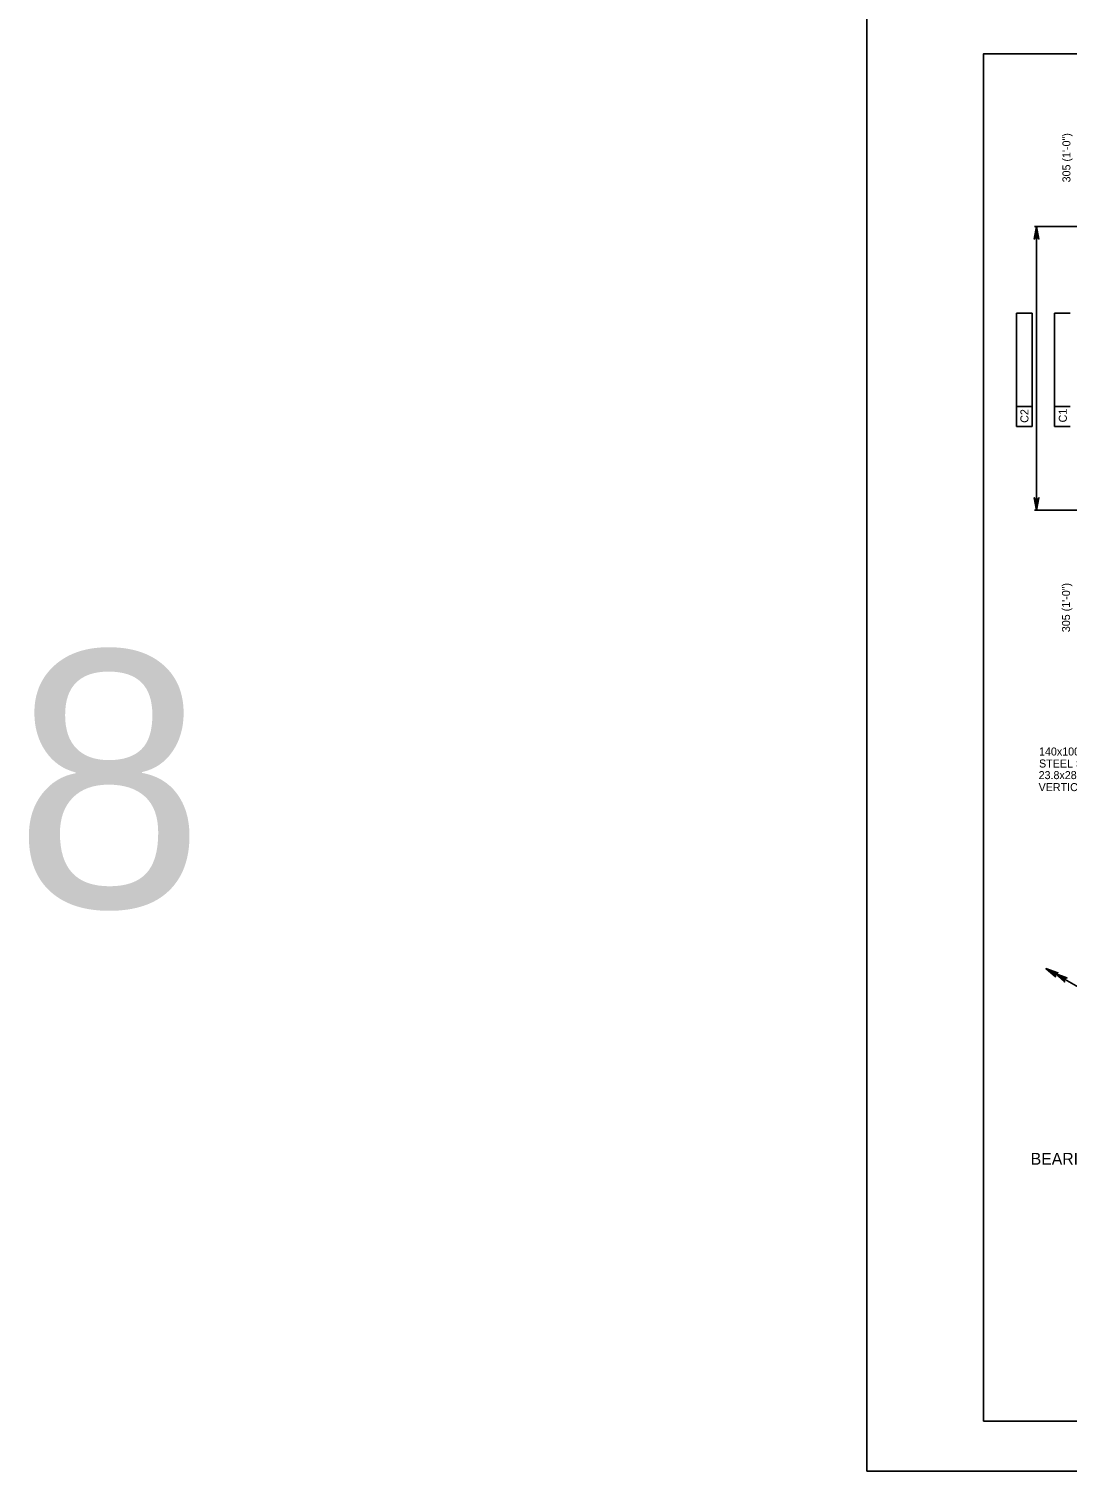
# Model space of a CAD drawing. Extents: x -13 to 81, y -176 to 0.
# Drawn here: x -12.57 to 3.01, y -176 to -154.38 of the extents above; entities that cross this region are included whole.
import ezdxf

# ---------------------------------------------------------------- set-up
doc = ezdxf.new("R2010")
doc.units = 0
for name, color, linetype in [('Level 1', 7, 'Continuous'), ('Level 4', 7, 'Continuous'), ('Level 62', 7, 'Continuous'), ('Level 63', 7, 'Continuous')]:
    doc.layers.add(name, color=color, linetype=linetype)

msp = doc.modelspace()

# ---------------------------------------------------------------- linework, layer by layer
at = {"layer": 'Level 1'}
msp.add_lwpolyline([(1.75, -175.25), (33.25, -175.25), (33.25, -154.75), (1.75, -154.75)], close=True, dxfattribs=at)
at = {"layer": 'Level 4'}
for p, q in [((7.263, -157.34), (2.518, -157.34)), ((2.547, -157.34), (2.547, -161.592)), ((2.483, -158.637), (2.247, -158.637)), ((2.247, -160.035), (2.247, -158.637)), ((2.483, -160.338), (2.483, -158.637)), ((3.05, -158.637), (2.814, -158.637)), ((2.814, -160.035), (2.814, -158.637)), ((2.247, -160.338), (2.247, -160.035)), ((2.483, -160.035), (2.247, -160.035)), ((2.814, -160.338), (2.814, -160.035)), ((3.05, -160.035), (2.814, -160.035)), ((2.247, -160.338), (2.483, -160.338)), ((2.814, -160.338), (3.05, -160.338)), ((9.603, -161.592), (2.518, -161.592)), ((2.688, -168.464), (5.312, -169.971))]:
    msp.add_line(p, q, dxfattribs=at)
for points in [[(2.547, -157.34), (2.582, -157.527), (2.572, -157.513), (2.56, -157.505), (2.547, -157.503), (2.535, -157.505), (2.522, -157.513), (2.512, -157.527), (2.547, -157.34), (2.522, -157.513), (2.535, -157.505), (2.547, -157.34), (2.547, -157.503), (2.56, -157.505), (2.547, -157.34), (2.572, -157.513)], [(2.547, -161.592), (2.512, -161.406), (2.522, -161.42), (2.535, -161.428), (2.547, -161.43), (2.56, -161.428), (2.572, -161.42), (2.582, -161.406), (2.547, -161.592), (2.572, -161.42), (2.56, -161.428), (2.547, -161.592), (2.547, -161.43), (2.535, -161.428), (2.547, -161.592), (2.522, -161.42)], [(2.688, -168.464), (2.833, -168.588), (2.825, -168.572), (2.825, -168.557), (2.829, -168.545), (2.837, -168.536), (2.85, -168.528), (2.867, -168.527), (2.688, -168.464), (2.85, -168.528), (2.837, -168.536), (2.688, -168.464), (2.829, -168.545), (2.825, -168.557), (2.688, -168.464), (2.825, -168.572)], [(2.824, -168.541), (2.968, -168.665), (2.961, -168.649), (2.961, -168.634), (2.965, -168.622), (2.973, -168.613), (2.986, -168.606), (3.003, -168.604), (2.824, -168.541), (2.986, -168.606), (2.973, -168.613), (2.824, -168.541), (2.965, -168.622), (2.961, -168.634), (2.824, -168.541), (2.961, -168.649)]]:
    msp.add_lwpolyline(points, dxfattribs=at)
at = {"layer": 'Level 62'}
msp.add_line((0, -176), (0, -176), dxfattribs=at)
at = {"layer": 'Level 63'}
msp.add_lwpolyline([(0, -176), (34, -176), (34, -154), (0, -154)], close=True, dxfattribs=at)

# ---------------------------------------------------------------- texts
at = {"layer": 'Level 4'}
for s, rotation, p in [('305 (1\'-0")', 90, (3.055, -156.677)), ('C2', 89.9382, (2.425, -160.282)), ('C1', 89.9382, (3.001, -160.276)), ('305 (1\'-0")', 90, (3.049, -163.421))]:
    msp.add_text(s, height=0.12, rotation=rotation, dxfattribs=at).set_placement(p)
for s, height, p in [('8', 3.84, (-12.793, -167.544)), ('140x100x12 (5 1/2"x4"x1/2")', 0.12, (2.584, -165.27)), ('STEEL SIDE P, WITH', 0.12, (2.584, -165.45)), ('23.8x28.6 (15/16"x1 1/8")', 0.12, (2.578, -165.624)), ('VERTICAL SLOT (TYP.)', 0.12, (2.578, -165.804)), ('BEARING PLAN DETAIL', 0.17717, (2.459, -171.405))]:
    msp.add_text(s, height=height, dxfattribs=at).set_placement(p)

doc.saveas('drawing.dxf')
